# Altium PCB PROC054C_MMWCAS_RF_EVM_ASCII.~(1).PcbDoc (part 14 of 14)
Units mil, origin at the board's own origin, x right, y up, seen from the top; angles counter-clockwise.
Board outline 6299.21 x 5370.07 mil, 8 copper layers (L1 TOP, L2 GND, L3 SIGNAL 1, L4 GND, L5 SIGNAL 2, L6 SIGNAL 3, L7 GND, L8 BOTTOM), stack 53.5 mil thick; 775 components, 552 nets, 2648 pads, 7845 vias.
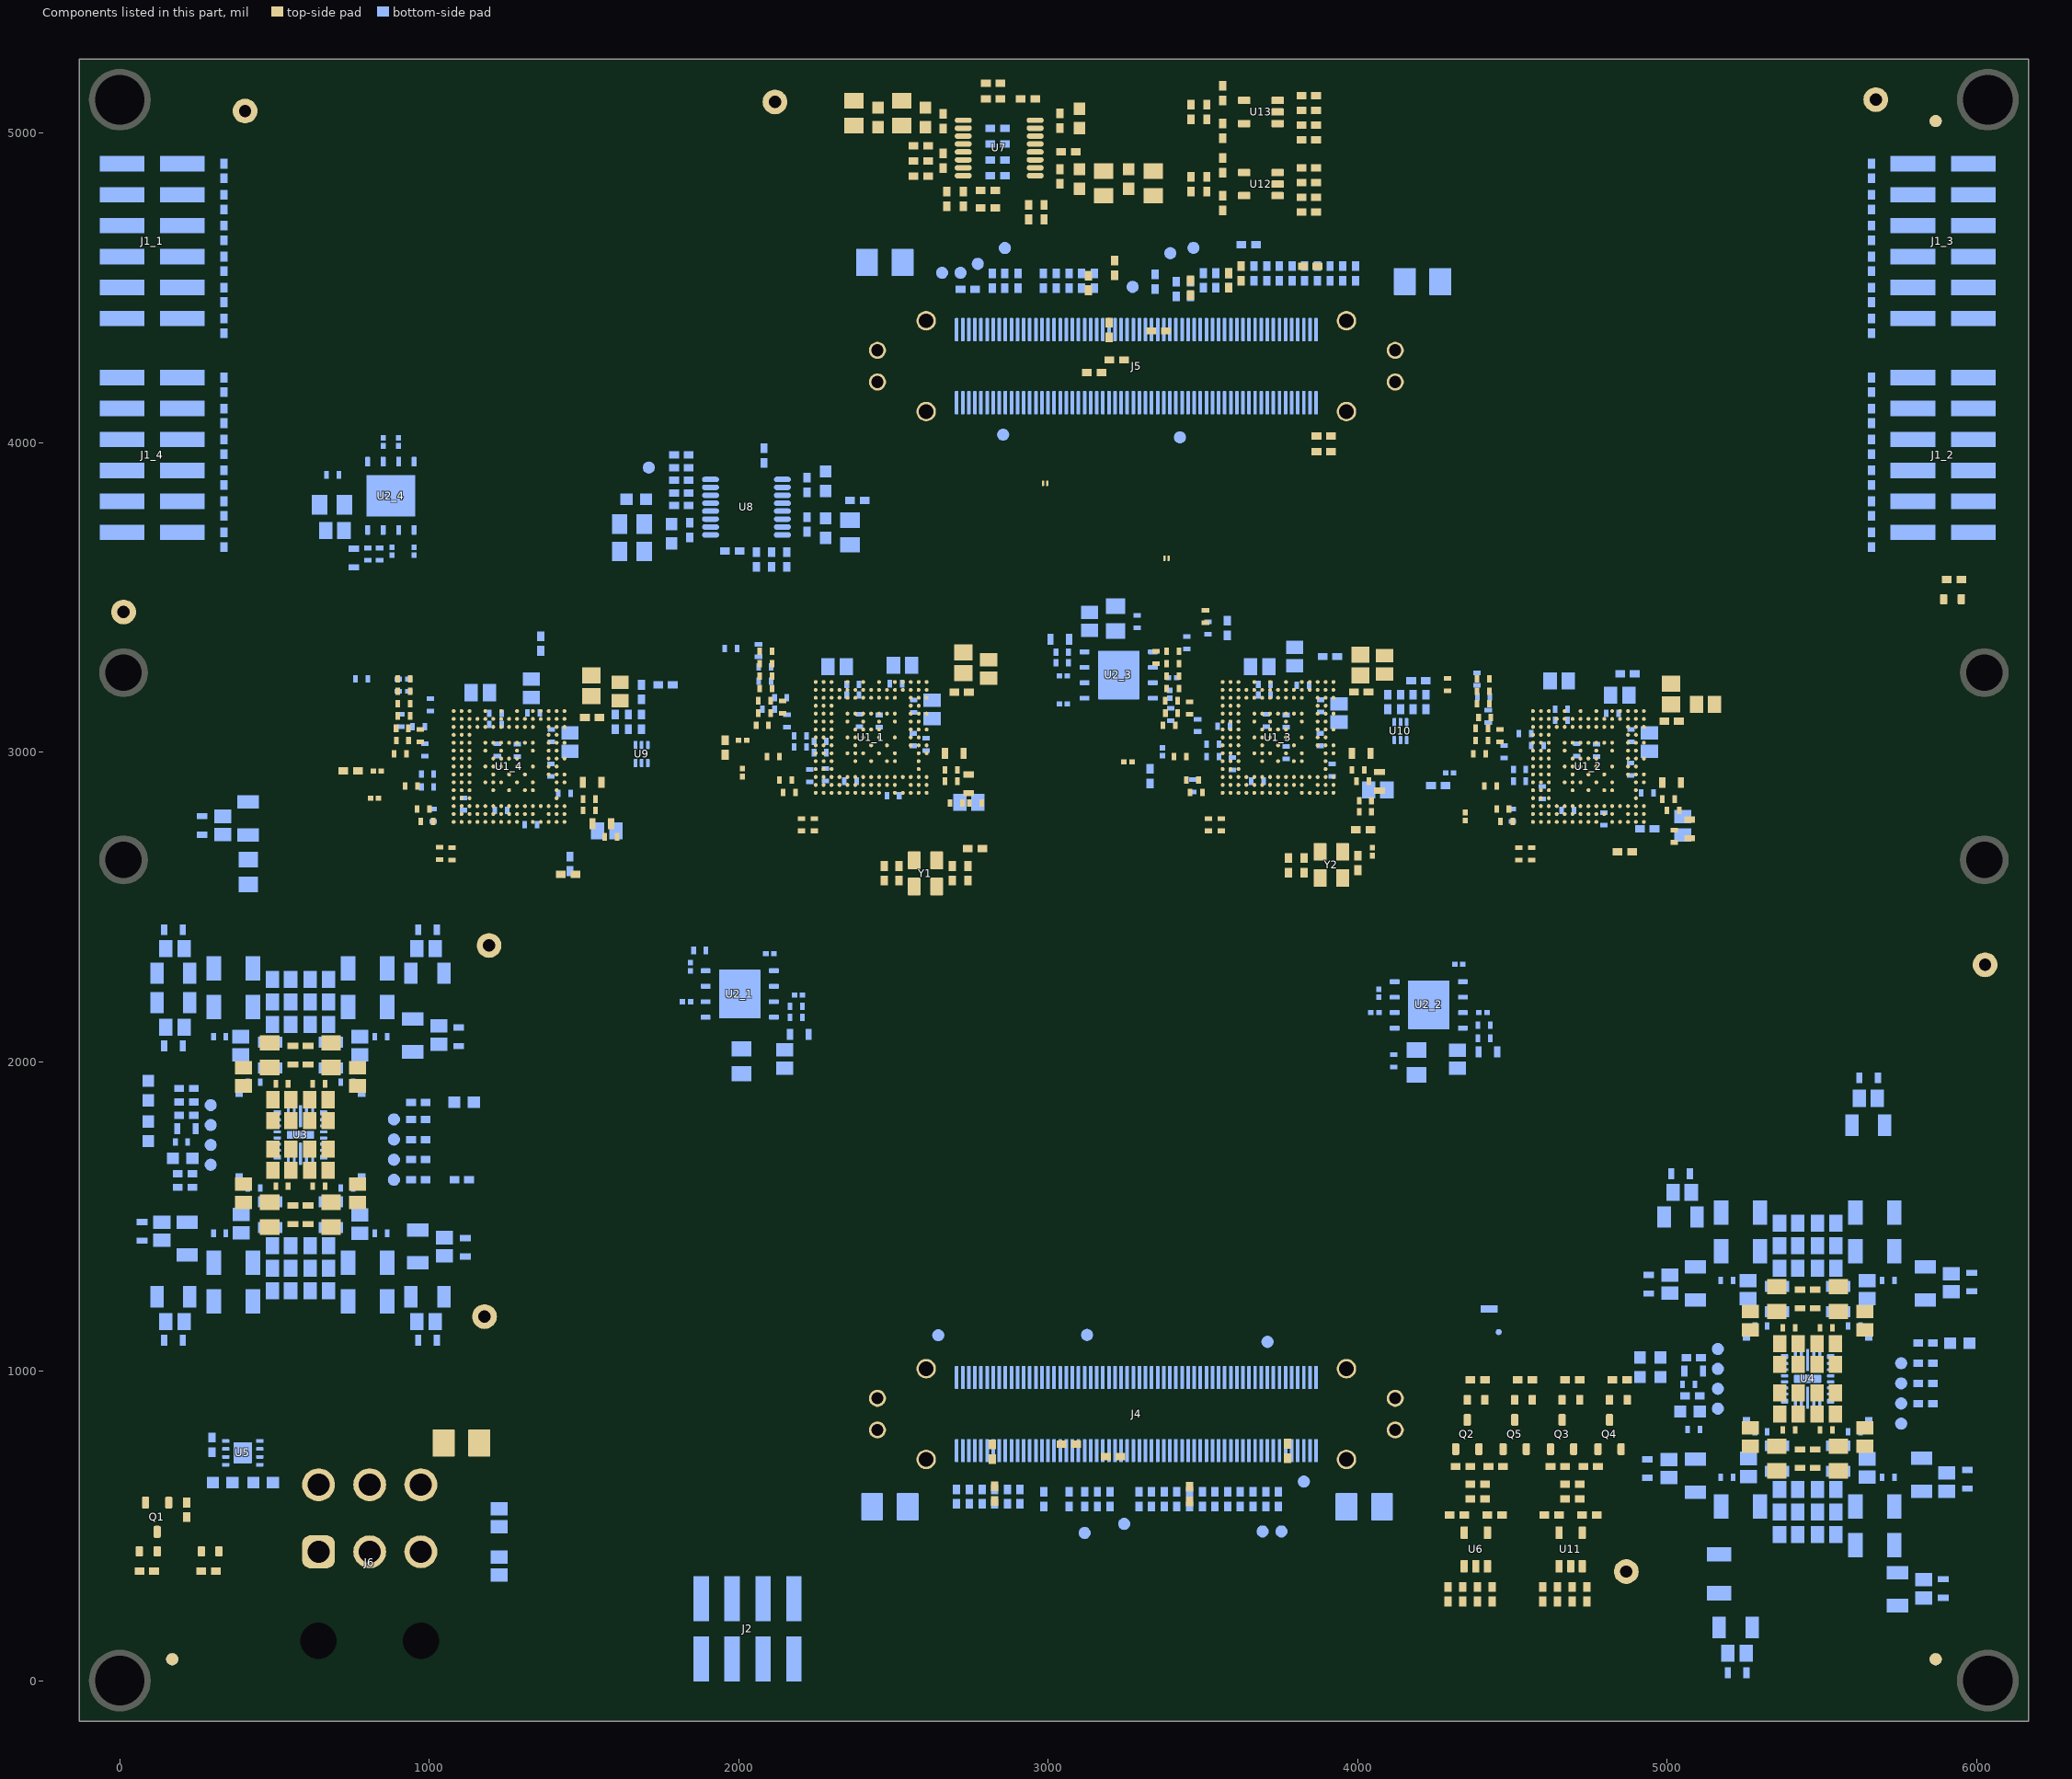
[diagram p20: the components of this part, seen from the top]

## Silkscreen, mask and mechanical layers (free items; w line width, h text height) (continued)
M5 Assembly Top:
  lines w5: 583.54,1762.96 583.54,2206.19 ; 5554.26,975.11 5554.26,1418.34
  lines w10: -423,-1061.17 6177,-1061.17 ; -423,-857.83 6179,-857.83 ; -423,-654.5 -423,-1264.5 3582,-1264.5 6179,-1264.5 6179,-654.5 -422.5,-654.5 -422.5,-1264.5 1153,-1264.5 ; 2042,-1264.5 2042,-654.5 ; 3309,-857.83 3309,-654.5 ; 4149,-857.83 4149,-654.5 ; 4771,-1271 4771,-1068.17
  text "COMPONENTS MARKED 'DNP' SHOULD NOT BE POPULATED." at 1022.5,-449.5 h60
  text "ASSEMBLY VARIANT:" at 1022,-565 h60
  text ".VariantName" at 2058,-565 h60
  text "PCB VIEWED FROM TOP SIDE" at -359.5,-786.67 h60
  text "BOARD #:" at 2117,-786.67 h60
  text ".PRJ_Number" at 2662.5,-786.67 h60
  text "REV:" at 3507,-786.67 h60
  text ".PCB_Rev" at 3798.5,-786.67 h60
  text "SVN REV:" at 4345,-786.67 h60
  text ".VersionControl_RevNumber" at 4851,-786.67 h60
  text "PLOT NAME =" at -359.5,-1195.34 h60
  text ".plot_File_Name" at 446,-1195.34 h60
  text "GENERATED    :" at 2119,-1195.34 h60
  text ".Print_Date" at 2988.5,-1195.34 h60
  text ".Print_Time" at 3717.5,-1195.34 h60
  text "TEXAS INSTRUMENTS" at 4982,-1195.34 h60
M6 Assembly Bottom:
  lines w10: -423.5,-858.33 6178.5,-858.33 ; -421.5,-1061.67 6178.5,-1061.67 ; 984.5,-1271.5 984.5,-1068.67 ; 1606.5,-858.33 1606.5,-655 ; 2446.5,-858.33 2446.5,-655 ; 3713.5,-1265 3713.5,-655 ; 4602.5,-1265 6178,-1265 6178,-655 -423.5,-655 -423.5,-1265 2173.5,-1265 6178.5,-1265 6178.5,-655
  text "COMPONENTS MARKED 'DNP' SHOULD NOT BE POPULATED." at 5971,-449 h60
  text ".VariantName" at 4927,-565 h60
  text "ASSEMBLY VARIANT:" at 5966,-565 h60
  text ".VersionControl_RevNumber" at 904.5,-787.17 h60
  text "SVN REV:" at 1410.5,-787.17 h60
  text ".PCB_Rev" at 1957,-787.17 h60
  text "REV:" at 2248.5,-787.17 h60
  text ".PRJ_Number" at 3093,-787.17 h60
  text "BOARD #:" at 3638.5,-787.17 h60
  text "PCB VIEWED FROM BOTTOM SIDE" at 6115,-787.17 h60
  text "TEXAS INSTRUMENTS" at 773.5,-1195.84 h60
  text ".Print_Time" at 2038,-1195.84 h60
  text ".Print_Date" at 2767,-1195.84 h60
  text "GENERATED    :" at 3636.5,-1195.84 h60
  text ".plot_File_Name" at 5309.5,-1195.84 h60
  text "PLOT NAME =" at 6115,-1195.84 h60
M9 Title Sheet:
  drawing of 56 lines, arcs and shapes, not listed
  text "1" at 1258.5,13245 h70
  text "2" at 5253.5,13245 h70
  text "3" at 9248.5,13245 h70
  text "4" at 13249.51,13245 h70
  text "5" at 17247.84,13245 h70
  text "B" at -598.5,10847 h70
  text "B" at 19101.5,10847 h70
  text "C" at -598.5,5847 h70
  text "C" at 19101.5,5847 h70
  text "D" at -598.5,847 h70
  text "D" at 19101.5,847 h70
  text "PROJECT TITLE:" at 16016.5,137.61 h45
  text ".PRJ_Title" at 16066.5,4.28 h70
  text "DESIGNED FOR:" at 16016.5,-163.39 h45
  text ".PRJ_Customer" at 16066.5,-303.39 h70
  text "FILE NAME:" at 16016.5,-463.39 h45
  text ".PCB_File_Name_No_Path" at 16066.5,-583.39 h70
  text "Texas Instruments (TI) and/or its licensors do not warrant the accuracy or completeness of this specification" at 11047,-745.23 h45
  text "ENGINEER:" at 16016.5,-753.39 h45
  text "LAYOUT BY:" at 17521.5,-753.39 h45
  text "or any information contained therein. TI and/or its licensors do not warrant that this design will meet" at 11002.01,-857.89 h45
  text ".PRJ_Engineer" at 16066.5,-908.38 h70
  text ".PCB_Layout" at 17572,-908.38 h70
  text "the specifications, will be suitable for your application or fit for any particular purpose, or will operate in" at 11002.01,-970.56 h45
  text ".Layer_Name" at 445.07,-990.08 h60
  text "ALTIUM DESIGNER VERSION:" at 17521.5,-1063.39 h45
  text "an implementation. TI and/or its licensors do not warrant that the design is production worthy. You should" at 11002.01,-1083.22 h45
  text "completely validate and test your design implementation to confirm the system functionality for your application." at 11047,-1195.89 h45
  text ".print_Scale" at 16066.5,-1196.72 h70
  text ".Application_BuildNumber" at 17572,-1196.72 h70
  text "1" at 1258.5,-1450 h70
  text "2" at 5253.5,-1450 h70
  text "3" at 9248.5,-1450 h70
  text "4" at 13249.51,-1450 h70
  text "WO#307308-7306-D" at 16509.44,-1456.87 h70
  text "5" at 15928.92,-1461.99 h70
M10 Fab Notes:
  drawing of 216 lines, arcs and shapes, not listed
  text "NOTES: UNLESS OTHERWISE SPECIFIED." at 7740.21,11288.74 h100
  text "1. ALL VIAS ARE TENTED ON BOTH SIDES UNLESS SOLDERMASK OPENED IN GERBER." at 7734.62,10999.71 h100
  text "2. THE SOLDER MASK IMAGES THAT ARE THE SAME SIZE AS THE COMPONENT PADS MAY BE ENLARGED AS" at 7737.72,10701.92 h100
  text "PER THE MANUFACTURING CAPABILITIES BUT NOT BEYOND 0.08MM PER SIDE OR 0.15MM OVERALL." at 7933.15,10394.82 h100
  text "ALL OTHER SOLDER MASK IMAGES SHALL NOT BE MODIFIED." at 7939.35,10115.63 h100
  text "3. TRACE WIDTH SHOULD BE ACCURATELY ETCHED. MAX TOLERANCE +/- 1 MIL" at 7741.09,9826.69 h100
  text "FOR ETCHING ACCURACY NEAR THE ANTENNA REFER \"ANTENNA_ETCHING_REQUIREMENTS\" DOCUMENT" at 7956.31,9585.54 h100
  text "4. 5.9MIL VIA ONLY ON PAD SHOULD BE FILLED WITH CONDUCTIVE COPPER AND SURFACE SHOULD BE FLAT." at 7742.69,9332.2 h100
  text "FLATNESS TOLERANCE FOR VIA ON PADS: +0.000 /- 0.001 INCHES ON TOP SIDE." at 7937.26,9042.52 h100
  text "5. BACKDRILLING  INFO: 12 MIL DRILL AND 24 MIL PAD NEED TO BE REMOVED FROM THE BOTTOM TO LAYER 4" at 7742.15,8723.15 h100
  text "USE 24MIL DRILL BIT FOR BACKDRILLING ABOVE MENTIONED DRILLS. VENDOR MUST CUT L4 AND MUST NOT CUT L3." at 7938.64,8492.11 h100
  text "6. PRINTED WIRING BOARD SHALL COMPLY WITH REQUIREMENTS OF ANSI/J-STD-003." at 7728.63,8233.42 h100
  text "7. BOW AND TWIST SHALL NOT EXCEED 0.7% OF LONGEST SIDE" at 7726.51,7988.21 h100
  text "8. R136/R140 REQUIRE SPECIAL ASSEMBLY ATTENTION DUE TO THEIR NO SOLDER-MASK, RF CONSTRUCTION." at 7725.01,7727.29 h100
  text "9. FOR ANY ASSEMBLY OR FABRICATION QUESTIONS PLEASE CONTACT THE RESPONSIBLE TI PCB DESIGN TEAM." at 7725.01,7526.46 h100
  text "IMPEDANCE TABLE" at 10341.65,6835.82 h100
  text "TRACE WIDTH" at 9801.45,6563.02 h80
  text "TRACE SPACING" at 10767.83,6563.1 h80
  text "IMPEDANCE" at 12107.94,6482.51 h80
  text "LAYER" at 9267.28,6467.85 h80
  text "(mil)" at 10040.49,6408.69 h80
  text "(mil)" at 11101.67,6409.34 h80
  text "DESIGN INFORMATION" at 17057.02,6234.17 h60
  text "-" at 11206.64,6200.31 h80
  text "10.5" at 10075.03,6192.7 h80
  text "50 OHM +/-10%" at 11902.68,6192.18 h80
  text "1" at 9424.7,6191.41 h80
  text "MIN. TRACK WIDTH:" at 16412.46,6102.05 h60
  text "4" at 17508.7,6102.05 h60
  text "MIL" at 17663.46,6102.05 h60
  text "5.5" at 11145.7,6035.7 h80
  text "6.5" at 10117.7,6028.58 h80
  text "1" at 9424.7,6026.25 h80
  text "100 OHM +/-10%" at 11874.69,6025.56 h80
  text "4" at 17507.39,5986.31 h60
  text "MIN. CLEARANCE:" at 16412.46,5977.92 h60
  text "MIL" at 17663.46,5977.92 h60
  text "-" at 11207.12,5870 h80
  text "5.1" at 10128.22,5861.56 h80
  text "50 OHM +/-10%" at 11903.16,5861.87 h80
  text "3" at 9424.7,5861.2 h80
  text "13.77" at 17373.96,5859.24 h60
  text "MIN. VIA PAD SIZE:" at 16412.46,5853.8 h60
  text "MIL" at 17663.46,5853.8 h60
  text "0.05mm (2MIL)" at 17107.46,5723.9 h60
  text "MINIMUM ANNULAR RING" at 16083.23,5715.67 h60
  text "EXTERNAL" at 17815.46,5715.67 h60
  text "-" at 11207.36,5704.84 h80
  text "12" at 10157.06,5697.26 h80
  text "50 OHM +/-10%" at 11903.4,5696.72 h80
  text "5" at 9424.7,5695.94 h80
  text "PER" at 16283.23,5605.55 h60
  text "IPC-D-275 CLASS 2 LEVEL C" at 16503.23,5605.54 h60
  text "-" at 11207.6,5539.69 h80
  text "6.9" at 10115.34,5536.24 h80
  text "50 OHM +/-10%" at 11903.64,5531.56 h80
  text "6" at 9424.7,5530.79 h80
  text "MIL, HOLES" at 17991.46,5505.07 h60
  text "+/-" at 17599,5496.48 h60
  text "+/-" at 18453,5496.48 h60
  text "REGISTRATION TOLERANCES:" at 16083.23,5495.42 h60
  text "METAL" at 17283,5495.42 h60
  text "2" at 17859.2,5495.42 h60
  text "3" at 18692.2,5495.42 h60
  text "MIL" at 18808.46,5495.42 h60
  text "HOLE SIZE TOLERANCE (UNLESS OTHERWISE SPECIFIED):" at 16083.23,5397.1 h60
  text "+/-" at 18453,5394.23 h60
  text "3" at 18692.2,5393.17 h60
  text "MIL" at 18808.46,5393.17 h60
  text "5" at 10173.32,5372.82 h80
  text "7" at 11206.57,5372.82 h80
  text "6" at 9424.7,5365.63 h80
  text "100 OHM +/-10%" at 11875.65,5364.94 h80
  text "MATERIAL:" at 16008.46,5255.52 h60
  text "-" at 11208.08,5209.37 h80
  text "7.75" at 10076.47,5201.76 h80
  text "50 OHM +/-10%" at 11904.12,5201.25 h80
  text "8" at 9424.7,5200.47 h80
  text "FR-4 High Tg" at 16994.9,5127 h60
  text "REFER STACKUP" at 18248.68,5125 h60
  text "X" at 17740.09,5121.5 h60
  text "FR-408" at 16429.46,5114.49 h60
  text "OTHER" at 17917.46,5114.49 h60
  text "6.75" at 11104.41,5039.74 h80
  text "8" at 9424.7,5035.32 h80
  text "100 OHM +/-10%" at 11876.13,5034.63 h80
  text "5.25" at 10072.43,5027.88 h80
  text "55MIL +/-10%" at 18338.77,4972.52 h60
  text "62 MIL (1.6mm) +/-10%" at 16749.56,4971.46 h60
  text "X" at 17922.86,4964.87 h60
  text "THICKNESS:" at 16083.23,4963.24 h60
  text "OTHER" at 18034.46,4963.24 h60
  text "TOLERANCE:" at 16083.23,4824.92 h60
  text "X" at 16931.46,4824.92 h60
  text "ANSI IPC-6012 TYPE 3 CLASS 2" at 17109.48,4824.92 h60
  text "OTHER +/-" at 17109.46,4680.73 h60
  text "BOW & TWIST:" at 16083.23,4535.54 h60
  text "ANSI IPC-6012 TYPE 3 CLASS 2" at 17109.48,4535.54 h60
  text "REFER NOTE 7" at 17696.51,4404.32 h60
  text "X" at 16932.7,4389.66 h60
  text "OTHER +/-" at 17109.46,4388.85 h60
  text "DRILLING:" at 16008.46,4258.23 h60
  text "NC_DRILL FILES" at 17769.46,4153.04 h60
  text "REFERENCE:" at 16083.23,4149.1 h60
  text "X" at 16740.46,4149.01 h60
  text "AS SHOWN" at 16918.46,4149.1 h60
  text "X" at 17641.46,4149.1 h60
  text "OTHER" at 18067.46,4006.85 h60
  text "PTH COPPER THICKNESS:" at 16082.91,4003.32 h60
  text "X" at 17222.14,4003.32 h60
  text "20-30 um" at 17350.14,4003.32 h60
  text "BOARD FINISH:" at 16008.46,3855.73 h60
  text "SILKSCREEN:" at 16163.68,3745.6 h60
  text "X" at 17121.46,3745.6 h60
  text "TOP" at 17238.46,3745.6 h60
  text "X" at 17631.46,3745.6 h60
  text "BOTTOM" at 17749.46,3745.6 h60
  text "SILKSCREEN COLOR:" at 16163.68,3590.41 h60
  text "X" at 17120.46,3590.41 h60
  text "WHITE" at 17238.46,3590.41 h60
  text "OTHER" at 17749.46,3590.41 h60
  text "X" at 17844.81,3454.25 h60
  text "RED" at 18395.4,3452.96 h60
  text "GREEN" at 17369.46,3446.96 h60
  text "OTHER" at 17987.46,3446.96 h60
  text "SOLDER RESIST COLOR:" at 16163.68,3440.1 h60
  text "X" at 17251.46,3292.71 h60
  text "MATTE" at 17369.46,3292.71 h60
  text "SEMI-GLOSS" at 17987,3292.07 h60
  text "IMMERSION GOLD (ENIG)" at 17069.46,3119.94 h60
  text "ENEPIG" at 18407,3112.72 h60
  text "SURFACE FINISH:" at 16008.46,3111.72 h60
  text "X" at 16183.74,2975.11 h60
  text "IMM. TIN/SILVER OR EQUIV" at 16338,2974.4 h60
  text "OTHER" at 17769.46,2970.47 h60
  text "ARRAY/PANEL:" at 16008.46,2815.09 h60
  text "CUT AND TRIM PER M1 BOARD OUTLINE" at 17069.46,2806.87 h60
  text "N.C. ROUTE" at 17069.46,2670.9 h60
  text "V. SCORE" at 17935.46,2670.9 h60
  text "CERTIFICATION:" at 16008.46,2541.77 h60
  text "MATERIALS AND WORKMANSHIP FOR ALL PCBS" at 16733.46,2541.77 h60
  text "TO MEET OR EXCEED THE REQUIREMENTS OF:" at 16733.46,2447.71 h60
  text "X" at 16370.97,2319.08 h60
  text "ANSI IPC-A-600F CLASS ->" at 16498.96,2319.08 h60
  text "X" at 18146.97,2319.08 h60
  text "2" at 18256.96,2319.08 h60
  text "1" at 17941.96,2317.58 h60
  text "3" at 18610.96,2317.58 h60
  text "X" at 17182.97,2171.39 h60
  text "RoHS" at 17310.96,2171.39 h60
  text "OTHER" at 17955.36,2171.39 h60
  text "PER ORDER" at 18352.42,2171.39 h60
  text "ALL BOARDS MUST MEET OR EXCEED UL94-V0 REQUIREMENTS." at 16036,2017.57 h60
  text "PCB MUST BEAR THE UL94V-0 UL REGISTERED MATERIAL ID NUMBER" at 16036,1901.5 h60
  text "ADDITIONAL REQUIREMENTS:" at 16008.46,1732.08 h60
  text "MICROSECTION:" at 16083.23,1624.95 h60
  text "YES" at 16988.96,1624.95 h60
  text "REQUIRED" at 17850.46,1480.62 h60
  text "BARE BOARD ELEC. TEST:" at 16083.23,1477.76 h60
  text "NONE" at 17388.96,1477.76 h60
  text "X" at 17732.46,1477.76 h60
  text "PER ORDER" at 18442.46,1477.76 h60
  text "XX MIL VIAS REQUIRE NON-CONDUCTIVE FILL AND PLANARIZE" at 16251.38,1272.82 h59
  text "XX MIL VIAS REQUIRE CONDUCTIVE FILL AND PLANARIZE" at 16259.38,1168.84 h60
  text "OUTER XX MIL TRACES REQUIRE 50 OHM SINGLE-ENDED IMPEDANCE" at 16258.39,1005.46 h56
  text "LAYER 2 & 3 (INNER LAYERS) XX MIL WIDE, XX MIL SPACE / TRACES REQUIRE 100 OHM DIFFERENTIAL IMPEDANCE" at 16250.39,769.74 h60
  text ".Layer_Name" at 445.07,-990.08 h60
M11 Gerber Information:
  lines w10: -423,-1061.17 6177,-1061.17 ; -423,-857.83 6179,-857.83 ; -423,-654.5 -423,-1264.5 3582,-1264.5 6179,-1264.5 6179,-654.5 -422.5,-654.5 -422.5,-1264.5 1153,-1264.5 ; 2042,-1264.5 2042,-654.5 ; 3309,-857.83 3309,-654.5 ; 4149,-857.83 4149,-654.5 ; 4771,-1271 4771,-1068.17
  text "ALL ARTWORK VIEWED FROM TOP SIDE" at -359.5,-786.67 h60
  text "BOARD #:" at 2117,-786.67 h60
  text ".PRJ_Number" at 2662.5,-786.67 h60
  text "REV:" at 3507,-786.67 h60
  text ".PCB_Rev" at 3798.5,-786.67 h60
  text "SVN REV:" at 4345,-786.67 h60
  text ".VersionControl_RevNumber" at 4851,-786.67 h60
  text "LAYER NAME =" at -359.5,-989.49 h60
  text "GENERATED    :" at 2119,-1195.34 h60
  text ".Print_Date" at 2988.5,-1195.34 h60
  text ".Print_Time" at 3717.5,-1195.34 h60
  text "TEXAS INSTRUMENTS" at 4982,-1195.34 h60
M12 Stackup:
  drawing of 509 lines, arcs and shapes, not listed
  text "STACKUP TABLE:" at 1737.57,11222.67 h100
  text "Layer" at 1767.62,11000.5 h60
  text "Name" at 2177.53,11000.5 h60
  text "Material" at 3107.27,11000.5 h60
  text "Thickness" at 3967.04,11000.5 h60
  text "Constant" at 4616.88,11000.5 h60
  text "Board Layer Stack" at 5186.74,11000.5 h60
  text "Top Overlay" at 2177.53,10880.5 h60
  text "Top Solder" at 2177.53,10760.5 h60
  text "Solder Resist" at 3107.27,10760.5 h60
  text "0.80mil" at 3967.04,10760.5 h60
  text "3.5" at 4616.88,10760.5 h60
  text "[L1-L8]" at 1455.7,10709.15 h50 r90
  text "[L1-L2]" at 1643.91,10709.41 h50 r90
  text "1" at 1767.62,10640.5 h60
  text "L1 TOP" at 2177.53,10640.5 h60
  text "Copper" at 3107.27,10640.5 h60
  text "1.60mil" at 3967.04,10640.5 h60
  text "Dielectric 1" at 2177.53,10520.5 h60
  text "RO3003" at 3107.27,10520.5 h60
  text "5.00mil" at 3967.04,10520.5 h60
  text "3" at 4616.88,10520.5 h60
  text "2" at 1767.62,10400.5 h60
  text "L2 GND" at 2177.53,10400.5 h60
  text "Copper" at 3107.27,10400.5 h60
  text "0.80mil" at 3967.04,10400.5 h60
  text "Dielectric2" at 2177.53,10280.5 h60
  text "RO4450F" at 3107.27,10280.5 h60
  text "5.00mil" at 3967.04,10280.5 h60
  text "4.2" at 4616.88,10280.5 h60
  text "3" at 1767.62,10160.5 h60
  text "L3 SIGNAL 1" at 2177.53,10160.5 h60
  text "Copper" at 3107.27,10160.5 h60
  text "0.60mil" at 3967.04,10160.5 h60
  text "Dielectric3" at 2177.53,10040.5 h60
  text "RO4835 LOPRO" at 3107.27,10040.5 h60
  text "10.70mil" at 3967.04,10040.5 h60
  text "3.66" at 4616.88,10040.5 h60
  text "4" at 1767.62,9920.5 h60
  text "L4 GND" at 2177.53,9920.5 h60
  text "Copper" at 3107.27,9920.5 h60
  text "0.60mil" at 3967.04,9920.5 h60
  text "Dielectric4" at 2177.53,9800.5 h60
  text "370HR" at 3107.27,9800.5 h60
  text "5.00mil" at 3967.04,9800.5 h60
  text "4.2" at 4616.88,9800.5 h60
  text "5" at 1767.62,9680.5 h60
  text "L5 SIGNAL 2" at 2177.53,9680.5 h60
  text "Copper" at 3107.27,9680.5 h60
  text "1.20mil" at 3967.04,9680.5 h60
  text "Dielectric5" at 2177.53,9560.5 h60
  text "370HR" at 3107.27,9560.5 h60
  text "10.00mil" at 3967.04,9560.5 h60
  text "4.34" at 4616.88,9560.5 h60
  text "6" at 1767.62,9440.5 h60
  text "L6 SIGNAL 3" at 2177.53,9440.5 h60
  text "Copper" at 3107.27,9440.5 h60
  text "0.60mil" at 3967.04,9440.5 h60
  text "Dielectric6" at 2177.53,9320.5 h60
  text "370HR" at 3107.27,9320.5 h60
  text "5.00mil" at 3967.04,9320.5 h60
  text "4.2" at 4616.88,9320.5 h60
  text "7" at 1767.62,9200.5 h60
  text "L7 GND" at 2177.53,9200.5 h60
  text "Copper" at 3107.27,9200.5 h60
  text "0.80mil" at 3967.04,9200.5 h60
  text "Dielectric7" at 2177.53,9080.5 h60
  text "370HR" at 3107.27,9080.5 h60
  text "5.00mil" at 3967.04,9080.5 h60
  text "4.34" at 4616.88,9080.5 h60
  text "8" at 1767.62,8960.5 h60
  text "L8 BOTTOM" at 2177.53,8960.5 h60
  text "Copper" at 3107.27,8960.5 h60
  text "1.60mil" at 3967.04,8960.5 h60
  text "Bottom Solder" at 2177.53,8840.5 h60
  text "Solder Resist" at 3107.27,8840.5 h60
  text "0.80mil" at 3967.04,8840.5 h60
  text "3.5" at 4616.88,8840.5 h60
  text "Bottom Overlay" at 2177.53,8720.5 h60
  text "THIS IS AN IMPEDANCE CONTROLLED BOARD" at 2805.48,8474.5 h70
  text "NOTE:" at 1736.06,8322.35 h70
  text "1. EXTERNAL LAYER CU THICKNESS ARE FINISHED THICKNESS AFTER PLATING." at 1733.81,8177 h70
  text ".Layer_Name" at 445.07,-990.08 h60
M13 Component Bodies Top:
  text ".Layer_Name" at 446,-989.49 h60
M14 Component Bodies Bottom:
  text ".Layer_Name" at 446,-989.49 h60
M15 Courtyards Top:
  text ".Layer_Name" at 446,-989.49 h60
M16 Courtyards Bottom:
  text ".Layer_Name" at 446,-989.49 h60
Drill Drawing:
  lines w15: 7859.1,2506.49 13341.59,2506.49 ; 7859.1,4156.49 13341.59,4156.49 ; 7864.07,1130.87 13226.59,1130.87 ; 7864.07,1280.87 13226.59,1280.87 ; 8409.98,2356.49 8409.98,4306.49 ; 8414.95,980.87 8414.95,1430.87 ; 9069.8,2356.49 9069.8,4306.49 ; 9074.77,980.87 9074.77,1430.87 ; 10104.47,980.87 10104.47,1430.87 ; 10219.46,2356.49 10219.46,4306.49 ; 11294.12,980.87 11294.12,1430.87 ; 11409.12,2356.49 11409.12,4306.49 ; 11800,980.87 11800,1430.87 ; 11914.99,2356.49 11914.99,4306.49 ; 7859.1,2356.49 13341.59,2356.49 13341.59,4306.49 7859.1,4306.49 7859.1,2356.49 ; 7864.07,980.87 13226.59,980.87 13226.59,1430.87 7864.07,1430.87 7864.07,980.87
  text "Symbol" at 7949.1,4201.49 h72
  text "Count" at 8454.98,4201.49 h72
  text "Hole Size" at 9114.8,4201.49 h72
  text "Drill Layer Pair" at 10264.46,4201.49 h72
  text "Plated" at 11454.12,4201.49 h72
  text "Hole Tolerance(mil)" at 11959.99,4201.49 h72
  text "60" at 8454.98,4051.49 h60
  text "7.87mil (0.200mm)" at 9114.8,4051.49 h60
  text "L1 TOP - L8 BOTTOM" at 10264.46,4051.49 h60
  text "PTH" at 11454.12,4051.49 h60
  text "+0/-7.87" at 11959.99,4051.49 h60
  text "L" at 7920.01,4041.5 h66.67
  text "727" at 8454.98,3901.49 h60
  text "8.00mil (0.203mm)" at 9114.8,3901.49 h60
  text "L1 TOP - L8 BOTTOM" at 10264.46,3901.49 h60
  text "PTH" at 11454.12,3901.49 h60
  text "+0/-8" at 11959.99,3901.49 h60
  text "B" at 7920.01,3891.5 h66.67
  text "13" at 8454.98,3751.49 h60
  text "12.00mil (0.305mm)" at 9114.8,3751.49 h60
  text "L1 TOP - L8 BOTTOM" at 10264.46,3751.49 h60
  text "PTH" at 11454.12,3751.49 h60
  text "+0/-12" at 11959.99,3751.49 h60
  text "C" at 7920.01,3741.5 h66.67
  text "1522" at 8454.98,3601.49 h60
  text "12.20mil (0.310mm)" at 9114.8,3601.49 h60
  text "L1 TOP - L8 BOTTOM" at 10264.46,3601.49 h60
  text "PTH" at 11454.12,3601.49 h60
  text "+0/-12.2" at 11959.99,3601.49 h60
  text "D" at 7920.01,3591.5 h66.67
  text "8" at 8454.98,3451.49 h60
  text "39.37mil (1.000mm)" at 9114.8,3451.49 h60
  text "L1 TOP - L8 BOTTOM" at 10264.46,3451.49 h60
  text "PTH" at 11454.12,3451.49 h60
  text "+4/-0" at 11959.99,3451.49 h60
  text "E" at 7920.01,3441.5 h66.67
  text "8" at 8454.98,3301.49 h60
  text "40.00mil (1.016mm)" at 9114.8,3301.49 h60
  text "L1 TOP - L8 BOTTOM" at 10264.46,3301.49 h60
  text "PTH" at 11454.12,3301.49 h60
  text "+/-3" at 11959.99,3301.49 h60
  text "F" at 7920.01,3291.5 h66.67
  text "8" at 8454.98,3151.49 h60
  text "47.24mil (1.200mm)" at 9114.8,3151.49 h60
  text "L1 TOP - L8 BOTTOM" at 10264.46,3151.49 h60
  text "PTH" at 11454.12,3151.49 h60
  text "+4/-0" at 11959.99,3151.49 h60
  text "G" at 7920.01,3141.5 h66.67
  text "6" at 8454.98,3001.49 h60
  text "70.87mil (1.800mm)" at 9114.8,3001.49 h60
  text "L1 TOP - L8 BOTTOM" at 10264.46,3001.49 h60
  text "PTH" at 11454.12,3001.49 h60
  text "+/-2" at 11959.99,3001.49 h60
  text "H" at 7920.01,2991.5 h66.67
  text "2" at 8454.98,2851.49 h60
  text "118.11mil (3.000mm)" at 9114.8,2851.49 h60
  text "L1 TOP - L8 BOTTOM" at 10264.46,2851.49 h60
  text "NPTH" at 11454.12,2851.49 h60
  text "+/-2" at 11959.99,2851.49 h60
  text "I" at 7931.12,2841.5 h66.67
  text "4" at 8454.98,2701.49 h60
  text "118.11mil (3.000mm)" at 9114.8,2701.49 h60
  text "L1 TOP - L8 BOTTOM" at 10264.46,2701.49 h60
  text "PTH" at 11454.12,2701.49 h60
  text "+/-3" at 11959.99,2701.49 h60
  text "J" at 7920.01,2691.5 h66.67
  text "4" at 8454.98,2551.49 h60
  text "160.00mil (4.064mm)" at 9114.8,2551.49 h60
  text "L1 TOP - L8 BOTTOM" at 10264.46,2551.49 h60
  text "PTH" at 11454.12,2551.49 h60
  text "+/-3" at 11959.99,2551.49 h60
  text "K" at 7920.01,2541.5 h66.67
  text "2362 Total" at 8454.98,2401.49 h60
  text "Symbol" at 7954.07,1325.87 h72
  text "Count" at 8459.95,1325.87 h72
  text "Hole Size" at 9119.77,1325.87 h72
  text "Drill Layer Pair" at 10149.47,1325.87 h72
  text "Plated" at 11339.12,1325.87 h72
  text "Hole Tolerance(mil)" at 11845,1325.87 h72
  text "5523" at 8459.95,1175.87 h60
  text "5.90mil (0.150mm)" at 9119.77,1175.87 h60
  text "L1 TOP - L2 GND" at 10149.47,1175.87 h60
  text "PTH" at 11339.12,1175.87 h60
  text "+0/-5.9" at 11845,1175.87 h60
  text "A" at 7924.98,1165.88 h66.67
  text "5523 Total" at 8459.95,1025.87 h60
M17 Embedded Cavity:
  text ".Layer_Name" at 446,-989.49 h60
M18 Embedded Assembly:
  text ".Layer_Name" at 446,-989.49 h60
M19 Embedded Keepout:
  text ".Layer_Name" at 456,-979.49 h60
FAB1:
  lines w10: 7683.51,3722.81 7683.51,3828.33 7783.5,3828.33 7783.5,3722.81 7683.51,3722.81
  text "5" at 7713.99,3745.26 h60
  text "DRILL TABLE: (L1-L8)" at 7919.11,2131.89 h100
  text ".Layer_Name" at 456,-979.49 h60
  text "SHEET 1/2" at 18640.1,-1468.58 h70
FAB2:
  text "DRILL TABLE: (L1-L2)" at 7919.11,731.89 h100
  text ".Layer_Name" at 456,-979.49 h60
  text "SHEET 2/2" at 18640.1,-1468.58 h70

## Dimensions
-131,-131 to 0,0 on M2 Board Dimensions
-131,-131 to 0,0 on M2 Board Dimensions
0,0 to 6168.21,-131 on M2 Board Dimensions
0,0 to -131,5239.07 on M2 Board Dimensions
0,0 to 80.78,-77.36 on M2 Board Dimensions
